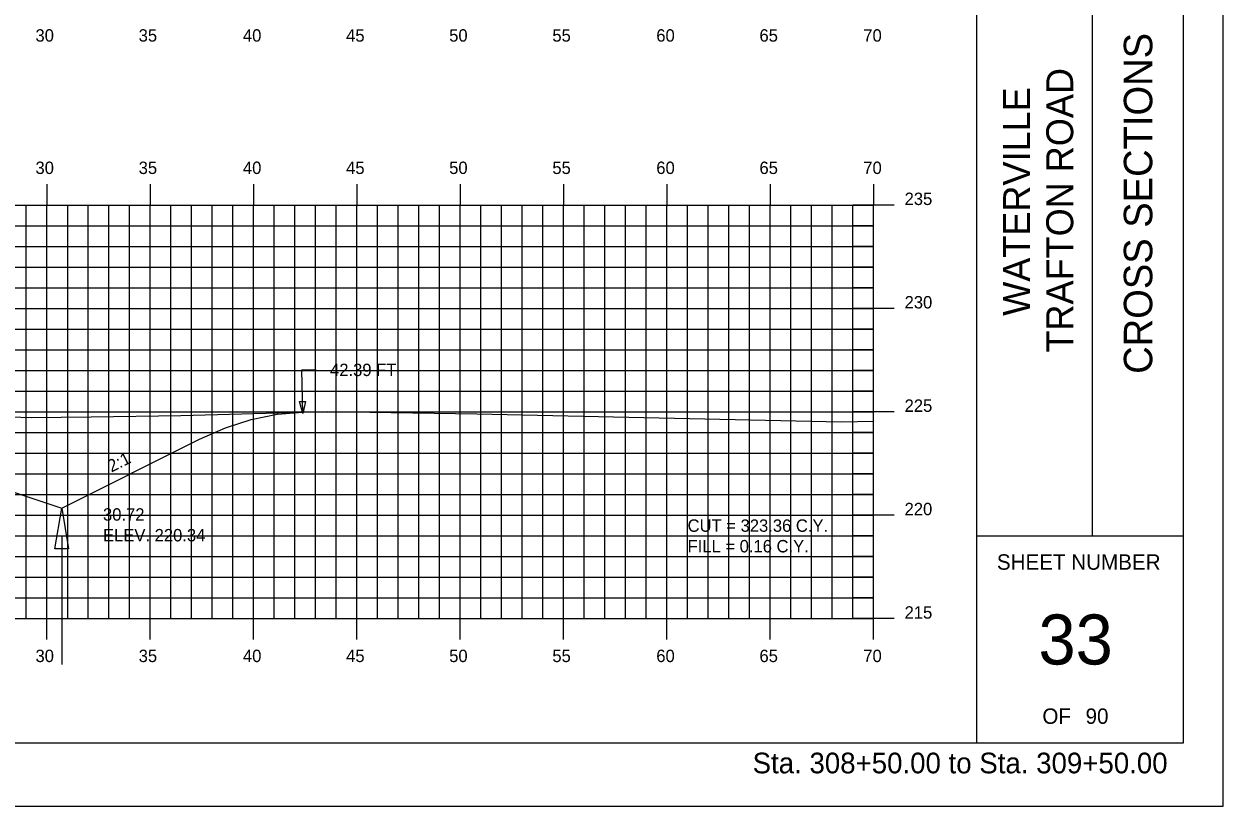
# Model space of a CAD drawing. Extents: x 1137876 to 1138046, y 608981 to 609091.
# Drawn here: x 1137988.1 to 1138046.1, y 608981.3 to 609019.1 of the extents above; entities that cross this region are included whole.
import ezdxf

# ---------------------------------------------------------------- set-up
doc = ezdxf.new("R2010")
doc.units = 0
for name, color, linetype in [('ANNOTATION', 7, 'Continuous'), ('BORDER', 7, 'Continuous'), ('D_Drainage_Ditch_Line', 7, 'Continuous'), ('D_Roadway_SlopeLines', 7, 'Continuous'), ('D_Text_Standard', 7, 'Continuous'), ('H_V ANNOTATION', 7, 'Continuous'), ('HIGHWAY_TITLE', 7, 'Continuous'), ('MAJOR', 7, 'Continuous'), ('MINOR', 7, 'Continuous'), ('PLOT BOUNDARY', 7, 'Continuous'), ('S_Roadway_Centerline', 7, 'Continuous')]:
    doc.layers.add(name, color=color, linetype=linetype)

msp = doc.modelspace()

# ---------------------------------------------------------------- linework, layer by layer
msp.add_lwpolyline([(1137920.838, 609001.638), (1137922.088, 609001.503), (1137923.338, 609001.228), (1137924.588, 609000.813), (1137925.838, 609000.258), (1137933.441, 608996.457), (1137936.441, 608997.457), (1137944.165, 609000.031), (1137944.166, 609000.031), (1137948.166, 609000.191), (1137959.166, 609000.411), (1137970.166, 609000.191), (1137977.166, 608999.911), (1137984.698, 608997.4), (1137989.882, 608995.673), (1137996.551, 608999.007), (1137997.801, 608999.558), (1137999.051, 608999.962), (1138000.301, 609000.217), (1138001.551, 609000.325)])
at = {"layer": 'BORDER'}
for p, q in [((1138034.166, 608984.335), (1138034.166, 609089.335)), ((1138039.757, 608994.338), (1138039.757, 609029.338)), ((1138034.166, 608994.338), (1138044.166, 608994.338))]:
    msp.add_line(p, q, dxfattribs=at)
msp.add_lwpolyline([(1137884.166, 608984.335), (1138044.166, 608984.335), (1138044.166, 609089.335), (1137884.166, 609089.335)], close=True, dxfattribs=at)
at = {"layer": 'D_Drainage_Ditch_Line'}
msp.add_line((1137989.882, 608994.36), (1137989.882, 608988.117), dxfattribs=at)
msp.add_lwpolyline([(1137990.21, 608993.704), (1137989.554, 608993.704), (1137989.882, 608995.673)], close=True, dxfattribs=at)
at = {"layer": 'D_Roadway_SlopeLines'}
for points in [[(1137989.882, 608995.673), (1137996.551, 608999.007), (1137997.801, 608999.558), (1137999.051, 608999.962), (1138000.301, 609000.217), (1138001.551, 609000.325)], [(1137984.698, 608997.4), (1137989.882, 608995.673)]]:
    msp.add_lwpolyline(points, dxfattribs=at)
at = {"layer": 'D_Text_Standard'}
msp.add_lwpolyline([(1138001.551, 609000.257), (1138001.508, 609002.364), (1138002.188, 609002.364)], dxfattribs=at)
msp.add_lwpolyline([(1138001.551, 609000.257), (1138001.394, 609000.836), (1138001.685, 609000.842)], close=True, dxfattribs=at)
at = {"layer": 'MAJOR'}
for p, q in [((1137989.166, 609011.337), (1137989.166, 609010.335)), ((1137994.166, 609011.337), (1137994.166, 609010.335)), ((1137999.166, 609011.337), (1137999.166, 609010.335)), ((1138004.166, 609011.337), (1138004.166, 609010.335)), ((1138009.166, 609011.337), (1138009.166, 609010.335)), ((1138014.166, 609011.337), (1138014.166, 609010.335)), ((1138019.166, 609011.337), (1138019.166, 609010.335)), ((1138024.166, 609011.337), (1138024.166, 609010.335)), ((1138029.166, 609011.337), (1138029.166, 609010.335)), ((1137889.166, 609010.335), (1138029.166, 609010.335)), ((1137889.166, 609010.335), (1138029.166, 609010.335)), ((1137989.166, 608990.335), (1137989.166, 609010.335)), ((1137994.166, 608990.335), (1137994.166, 609010.335)), ((1137999.166, 608990.335), (1137999.166, 609010.335)), ((1138004.166, 608990.335), (1138004.166, 609010.335)), ((1138009.166, 608990.335), (1138009.166, 609010.335)), ((1138014.166, 608990.335), (1138014.166, 609010.335)), ((1138019.166, 608990.335), (1138019.166, 609010.335)), ((1138024.166, 608990.335), (1138024.166, 609010.335)), ((1138030.168, 609010.335), (1138028.164, 609010.335)), ((1138029.166, 608990.335), (1138029.166, 609010.335)), ((1138029.166, 608990.335), (1138029.166, 609010.335)), ((1137889.166, 609005.335), (1138029.166, 609005.335)), ((1138030.168, 609005.335), (1138028.164, 609005.335)), ((1137889.166, 609000.335), (1138029.166, 609000.335)), ((1138030.168, 609000.335), (1138028.164, 609000.335)), ((1137889.166, 608995.335), (1138029.166, 608995.335)), ((1138030.168, 608995.335), (1138028.164, 608995.335)), ((1137889.166, 608990.335), (1138029.166, 608990.335)), ((1137889.166, 608990.335), (1138029.166, 608990.335)), ((1137989.166, 608989.333), (1137989.166, 608990.335)), ((1137994.166, 608989.333), (1137994.166, 608990.335)), ((1137999.166, 608989.333), (1137999.166, 608990.335)), ((1138004.166, 608989.333), (1138004.166, 608990.335)), ((1138009.166, 608989.333), (1138009.166, 608990.335)), ((1138014.166, 608989.333), (1138014.166, 608990.335)), ((1138019.166, 608989.333), (1138019.166, 608990.335)), ((1138024.166, 608989.333), (1138024.166, 608990.335)), ((1138030.168, 608990.335), (1138028.164, 608990.335)), ((1138029.166, 608989.333), (1138029.166, 608990.335))]:
    msp.add_line(p, q, dxfattribs=at)
at = {"layer": 'MINOR'}
for p, q in [((1137988.166, 608990.335), (1137988.166, 609010.335)), ((1137990.166, 609010.335), (1137990.166, 608990.335)), ((1137991.166, 608990.335), (1137991.166, 609010.335)), ((1137992.166, 608990.335), (1137992.166, 609010.335)), ((1137993.166, 608990.335), (1137993.166, 609010.335)), ((1137995.166, 608990.335), (1137995.166, 609010.335)), ((1137996.166, 608990.335), (1137996.166, 609010.335)), ((1137997.166, 608990.335), (1137997.166, 609010.335)), ((1137998.166, 608990.335), (1137998.166, 609010.335)), ((1138000.166, 608990.335), (1138000.166, 609010.335)), ((1138001.166, 608990.335), (1138001.166, 609010.335)), ((1138002.166, 608990.335), (1138002.166, 609010.335)), ((1138003.166, 608990.335), (1138003.166, 609010.335)), ((1138005.166, 608990.335), (1138005.166, 609010.335)), ((1138006.166, 608990.335), (1138006.166, 609010.335)), ((1138007.166, 608990.335), (1138007.166, 609010.335)), ((1138008.166, 608990.335), (1138008.166, 609010.335)), ((1138010.166, 608990.335), (1138010.166, 609010.335)), ((1138011.166, 608990.335), (1138011.166, 609010.335)), ((1138012.166, 608990.335), (1138012.166, 609010.335)), ((1138013.166, 608990.335), (1138013.166, 609010.335)), ((1138015.166, 608990.335), (1138015.166, 609010.335)), ((1138016.166, 608990.335), (1138016.166, 609010.335)), ((1138017.166, 608990.335), (1138017.166, 609010.335)), ((1138018.166, 608990.335), (1138018.166, 609010.335)), ((1138020.166, 608990.335), (1138020.166, 609010.335)), ((1138021.166, 608990.335), (1138021.166, 609010.335)), ((1138022.166, 608990.335), (1138022.166, 609010.335)), ((1138023.166, 608990.335), (1138023.166, 609010.335)), ((1138025.166, 608990.335), (1138025.166, 609010.335)), ((1138026.166, 608990.335), (1138026.166, 609010.335)), ((1138027.166, 608990.335), (1138027.166, 609010.335)), ((1138028.166, 608990.335), (1138028.166, 609010.335)), ((1137889.166, 609009.335), (1138029.166, 609009.335)), ((1138029.166, 609009.335), (1138028.164, 609009.335)), ((1137889.166, 609008.335), (1138029.166, 609008.335)), ((1138029.166, 609008.335), (1138028.164, 609008.335)), ((1137889.166, 609007.335), (1138029.166, 609007.335)), ((1138029.166, 609007.335), (1138028.164, 609007.335)), ((1137889.166, 609006.335), (1138029.166, 609006.335)), ((1138029.166, 609006.335), (1138028.164, 609006.335)), ((1137889.166, 609004.335), (1138029.166, 609004.335)), ((1138029.166, 609004.335), (1138028.164, 609004.335)), ((1137889.166, 609003.335), (1138029.166, 609003.335)), ((1138029.166, 609003.335), (1138028.164, 609003.335)), ((1137889.166, 609002.335), (1138029.166, 609002.335)), ((1138029.166, 609002.335), (1138028.164, 609002.335)), ((1137889.166, 609001.335), (1138029.166, 609001.335)), ((1138029.166, 609001.335), (1138028.164, 609001.335)), ((1137889.166, 608999.335), (1138029.166, 608999.335)), ((1138029.166, 608999.335), (1138028.164, 608999.335)), ((1137889.166, 608998.335), (1138029.166, 608998.335)), ((1138029.166, 608998.335), (1138028.164, 608998.335)), ((1137889.166, 608997.335), (1138029.166, 608997.335)), ((1138029.166, 608997.335), (1138028.164, 608997.335)), ((1137889.166, 608996.335), (1138029.166, 608996.335)), ((1138029.166, 608996.335), (1138028.164, 608996.335)), ((1137889.166, 608994.335), (1138029.166, 608994.335)), ((1138029.166, 608994.335), (1138028.164, 608994.335)), ((1137889.166, 608993.335), (1138029.166, 608993.335)), ((1138029.166, 608993.335), (1138028.164, 608993.335)), ((1137889.166, 608992.335), (1138029.166, 608992.335)), ((1138029.166, 608992.335), (1138028.164, 608992.335)), ((1137889.166, 608991.335), (1138029.166, 608991.335)), ((1138029.166, 608991.335), (1138028.164, 608991.335))]:
    msp.add_line(p, q, dxfattribs=at)
at = {"layer": 'PLOT BOUNDARY'}
msp.add_lwpolyline([(1137876.073, 608981.276), (1138046.073, 608981.276), (1138046.073, 609091.276), (1137876.073, 609091.276)], close=True, dxfattribs=at)
at = {"layer": 'S_Roadway_Centerline'}
msp.add_lwpolyline([(1137983.958, 609000.205), (1137988.409, 609000.056), (1137991.311, 609000.091), (1137995.652, 609000.165), (1138002.731, 609000.358), (1138009.962, 609000.234), (1138027.61, 608999.845), (1138029.166, 608999.884)], dxfattribs=at)

# ---------------------------------------------------------------- texts
at = {"layer": 'ANNOTATION'}
msp.add_text('2:1', height=0.6, rotation=26.56505, dxfattribs=at).set_placement((1137992.289, 608997.394))
at = {"layer": 'BORDER'}
msp.add_text('CROSS SECTIONS', height=1.37787, rotation=90, dxfattribs=at).set_placement((1138042.651, 609002.172))
for s, height, p in [('SHEET NUMBER', 0.74527, (1138035.132, 608992.701)), ('33', 2.4194, (1138037.142, 608988.118)), ('OF', 0.7453, (1138037.333, 608985.248)), ('90', 0.7453, (1138039.423, 608985.248))]:
    msp.add_text(s, height=height, dxfattribs=at).set_placement(p)
at = {"layer": 'D_Text_Standard'}
for s, p in [('42.39 FT', (1138002.868, 609002.064)), ('30.72', (1137991.882, 608995.073)), ('CUT = 323.36 C.Y.', (1138020.166, 608994.535)), ('ELEV. 220.34', (1137991.882, 608994.071)), ('FILL = 0.16 C.Y.', (1138020.166, 608993.539))]:
    msp.add_text(s, height=0.6, dxfattribs=at).set_placement(p)
at = {"layer": 'H_V ANNOTATION'}
for s, height, p in [('30', 0.6, (1137988.615, 609018.235)), ('35', 0.6, (1137993.607, 609018.235)), ('40', 0.6, (1137998.652, 609018.235)), ('45', 0.6, (1138003.644, 609018.235)), ('50', 0.6, (1138008.631, 609018.235)), ('55', 0.6, (1138013.623, 609018.235)), ('60', 0.6, (1138018.652, 609018.235)), ('65', 0.6, (1138023.644, 609018.235)), ('70', 0.6, (1138028.668, 609018.235)), ('30', 0.6, (1137988.615, 609011.835)), ('35', 0.6, (1137993.607, 609011.835)), ('40', 0.6, (1137998.652, 609011.835)), ('45', 0.6, (1138003.644, 609011.835)), ('50', 0.6, (1138008.631, 609011.835)), ('55', 0.6, (1138013.623, 609011.835)), ('60', 0.6, (1138018.652, 609011.835)), ('65', 0.6, (1138023.644, 609011.835)), ('70', 0.6, (1138028.668, 609011.835)), ('235', 0.6, (1138030.666, 609010.335)), ('230', 0.6, (1138030.666, 609005.335)), ('225', 0.6, (1138030.666, 609000.335)), ('220', 0.6, (1138030.666, 608995.335)), ('215', 0.6, (1138030.666, 608990.335)), ('30', 0.6, (1137988.615, 608988.235)), ('35', 0.6, (1137993.607, 608988.235)), ('40', 0.6, (1137998.652, 608988.235)), ('45', 0.6, (1138003.644, 608988.235)), ('50', 0.6, (1138008.631, 608988.235)), ('55', 0.6, (1138013.623, 608988.235)), ('60', 0.6, (1138018.652, 608988.235)), ('65', 0.6, (1138023.644, 608988.235)), ('70', 0.6, (1138028.668, 608988.235)), ('Sta. 308+50.00 to Sta. 309+50.00', 1.0002, (1138023.312, 608982.855))]:
    msp.add_text(s, height=height, dxfattribs=at).set_placement(p)
at = {"layer": 'HIGHWAY_TITLE'}
for s, height, p in [('TRAFTON ROAD', 1.30428, (1138038.825, 609003.201)), ('WATERVILLE', 1.3043, (1138036.739, 609004.98))]:
    msp.add_text(s, height=height, rotation=90, dxfattribs=at).set_placement(p)

doc.saveas('drawing.dxf')
